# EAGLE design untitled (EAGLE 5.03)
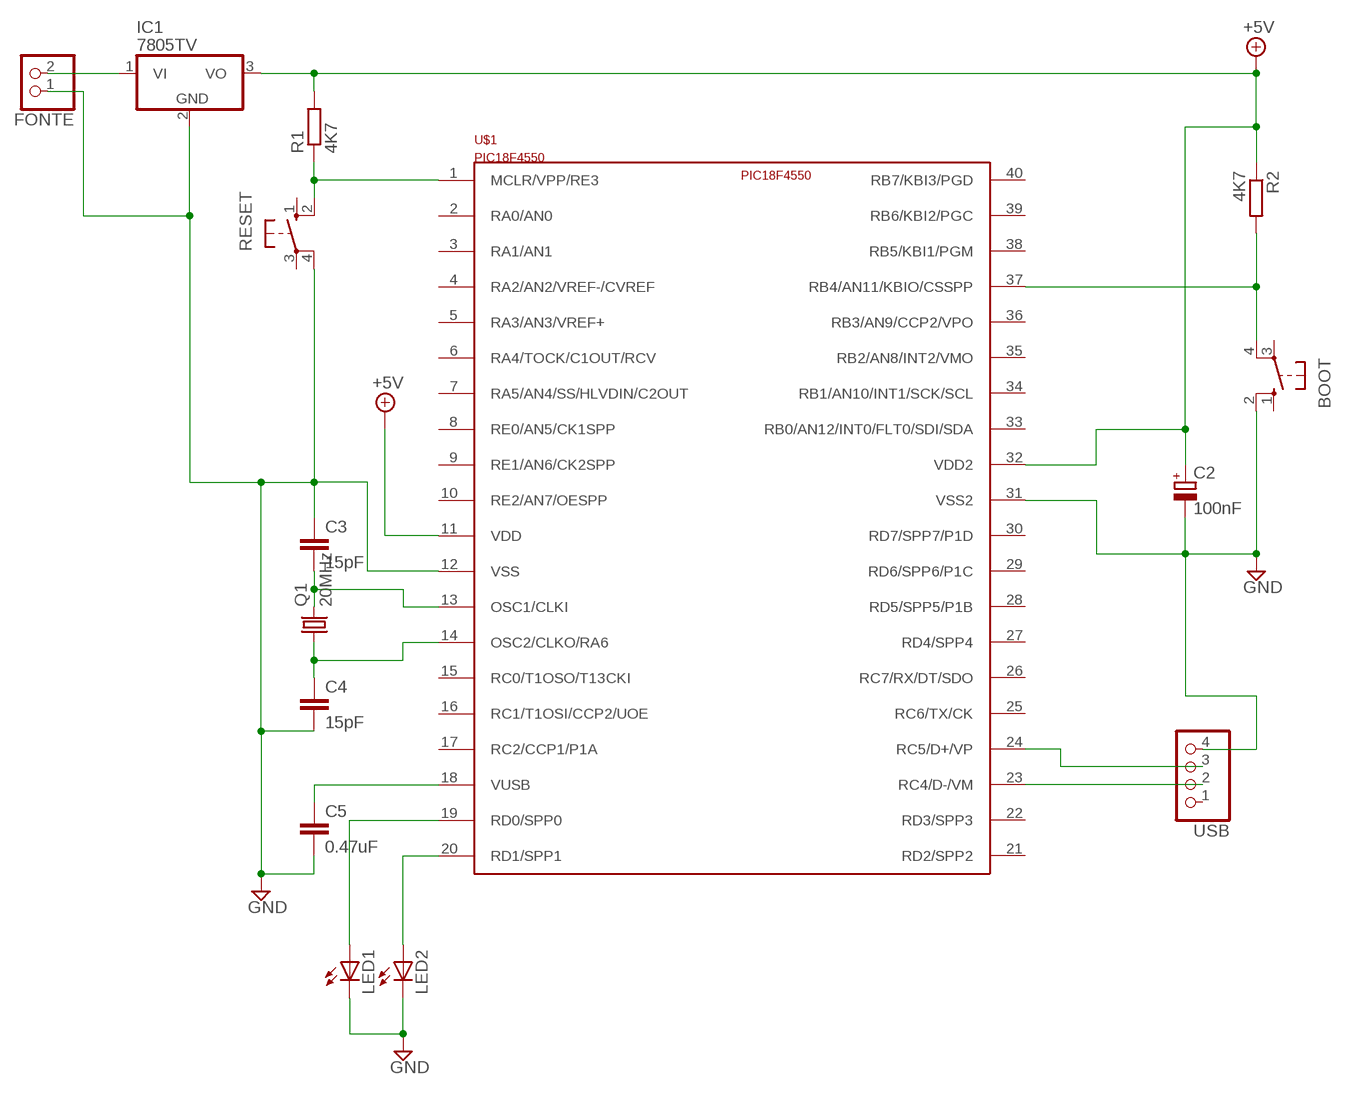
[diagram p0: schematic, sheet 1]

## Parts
BOOT  10-XX  [B3F-10XX]
C2  100nF  CPOL-EUE2,5-6E  [E2,5-6E]
C3  15pF  C-EU025-030X050  [C025-030X050]
C4  15pF  C-EU025-030X050  [C025-030X050]
C5  0.47uF  C-EU025-030X050  [C025-030X050]
FONTE  PINHD-1X2  [1X02]
IC1  7805TV  [TO220V]
LED1  LED5MM  [LED5MM]
LED2  LED5MM  [LED5MM]
Q1  20MHz  CRYSTALHC49S  [HC49/S]
R1  4K7  R-EU_0207/10  [0207/10]
R2  4K7  R-EU_0207/10  [0207/10]
RESET  10-XX  [B3F-10XX]
U$1  PIC18F4550  [PDIP-40]
USB  PINHD-1X4  [1X04]

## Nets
+5V: C2.+ IC1.3(VO) R1.2 R2.1 U$1.11(VDD) U$1.32(VDD2)
GND: BOOT.2(S1) C2.- C3.1 C4.2 C5.2 FONTE.1 IC1.2(GND) LED1.K(C) LED2.K(C) RESET.4(P1) U$1.12(VSS) U$1.31(VSS2) USB.4
N$1: C3.2 Q1.2 U$1.13(OSC1/CLKI)
N$2: C4.1 Q1.1 U$1.14(OSC2/CLKO/RA6)
N$3: R1.1 RESET.2(S1) U$1.1(MCLR/VPP/RE3)
N$4: FONTE.2 IC1.1(VI)
N$5: C5.1 U$1.18(VUSB)
N$8: U$1.23(RC4/D-/VM) USB.2
N$9: U$1.24(RC5/D+/VP) USB.3
N$10: LED1.A U$1.19(RD0/SPP0)
N$11: BOOT.4(P1) R2.2 U$1.37(RB4/AN11/KBIO/CSSPP)
N$12: LED2.A U$1.20(RD1/SPP1)
Unconnected: BOOT.1(S) BOOT.3(P) RESET.1(S) RESET.3(P) U$1.2(RA0/AN0) U$1.3(RA1/AN1) U$1.4(RA2/AN2/VREF-/CVREF) U$1.5(RA3/AN3/VREF+) U$1.6(RA4/TOCK/C1OUT/RCV) U$1.7(RA5/AN4/SS/HLVDIN/C2OUT) U$1.8(RE0/AN5/CK1SPP) U$1.9(RE1/AN6/CK2SPP) U$1.10(RE2/AN7/OESPP) U$1.15(RC0/T1OSO/T13CKI) U$1.16(RC1/T1OSI/CCP2/UOE) U$1.17(RC2/CCP1/P1A) U$1.21(RD2/SPP2) U$1.22(RD3/SPP3) U$1.25(RC6/TX/CK) U$1.26(RC7/RX/DT/SDO) U$1.27(RD4/SPP4) U$1.28(RD5/SPP5/P1B) U$1.29(RD6/SPP6/P1C) U$1.30(RD7/SPP7/P1D) U$1.33(RB0/AN12/INT0/FLT0/SDI/SDA) U$1.34(RB1/AN10/INT1/SCK/SCL) U$1.35(RB2/AN8/INT2/VMO) U$1.36(RB3/AN9/CCP2/VPO) U$1.38(RB5/KBI1/PGM) U$1.39(RB6/KBI2/PGC) U$1.40(RB7/KBI3/PGD) USB.1

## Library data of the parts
BOOT RESET = switch-omron:10-XX: OMRON SWITCH
C2 = resistor:CPOL-EU: POLARIZED CAPACITOR, European symbol
C3-C5 = resistor:C-EU: CAPACITOR, European symbol
FONTE = pinhead:PINHD-1X2: PIN HEADER
IC1 = linear:78*: Positive VOLTAGE REGULATOR Source: http://cache.national.com/ds/LM/LM78L05.pdf http://www.fairchildsemi.com/ds/LM/LM7805.pdf
LED1 LED2 = led:LED: LED
Q1 = crystal:CRYSTAL: CRYSTAL
R1 R2 = resistor:R-EU_: RESISTOR, European symbol
U$1 = pic18f4550:PIC18F4550
USB = pinhead:PINHD-1X4: PIN HEADER

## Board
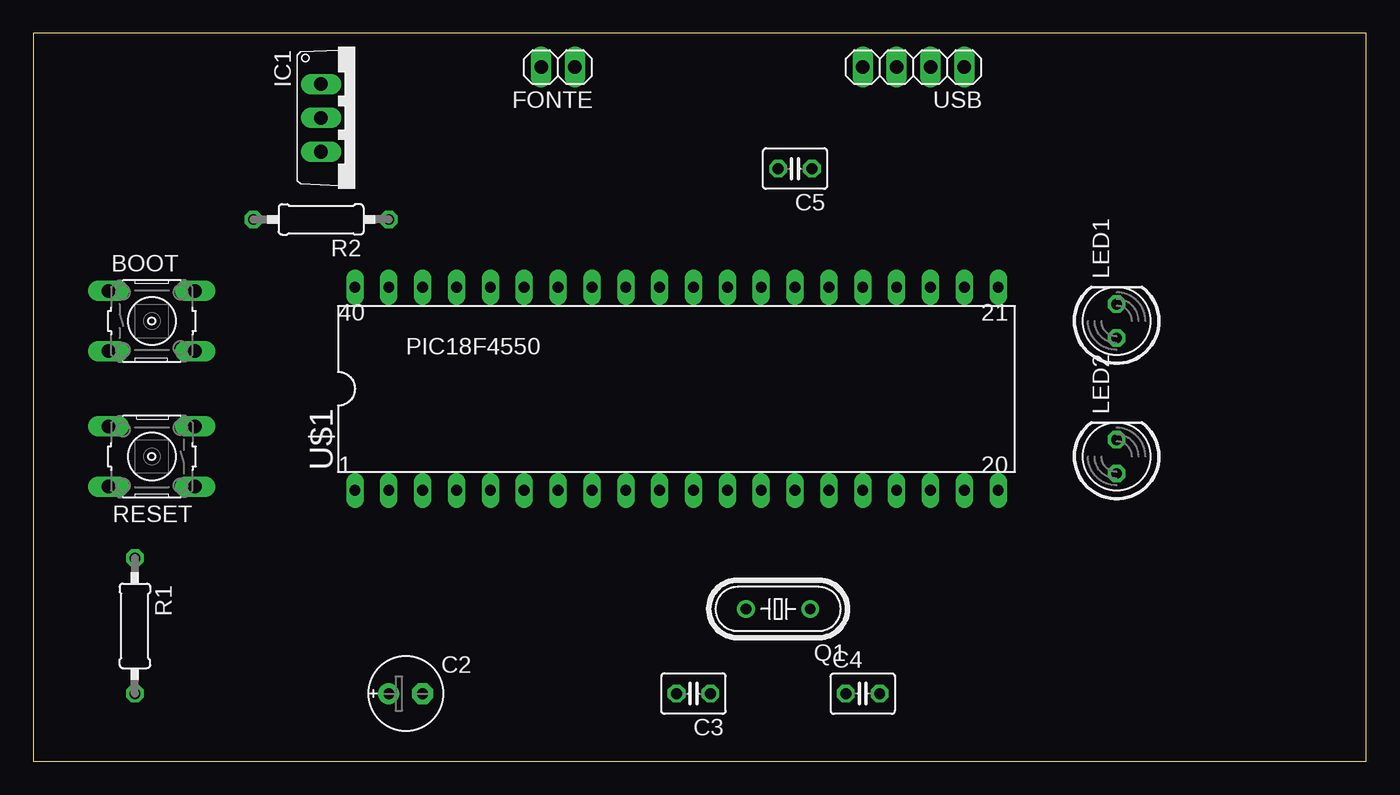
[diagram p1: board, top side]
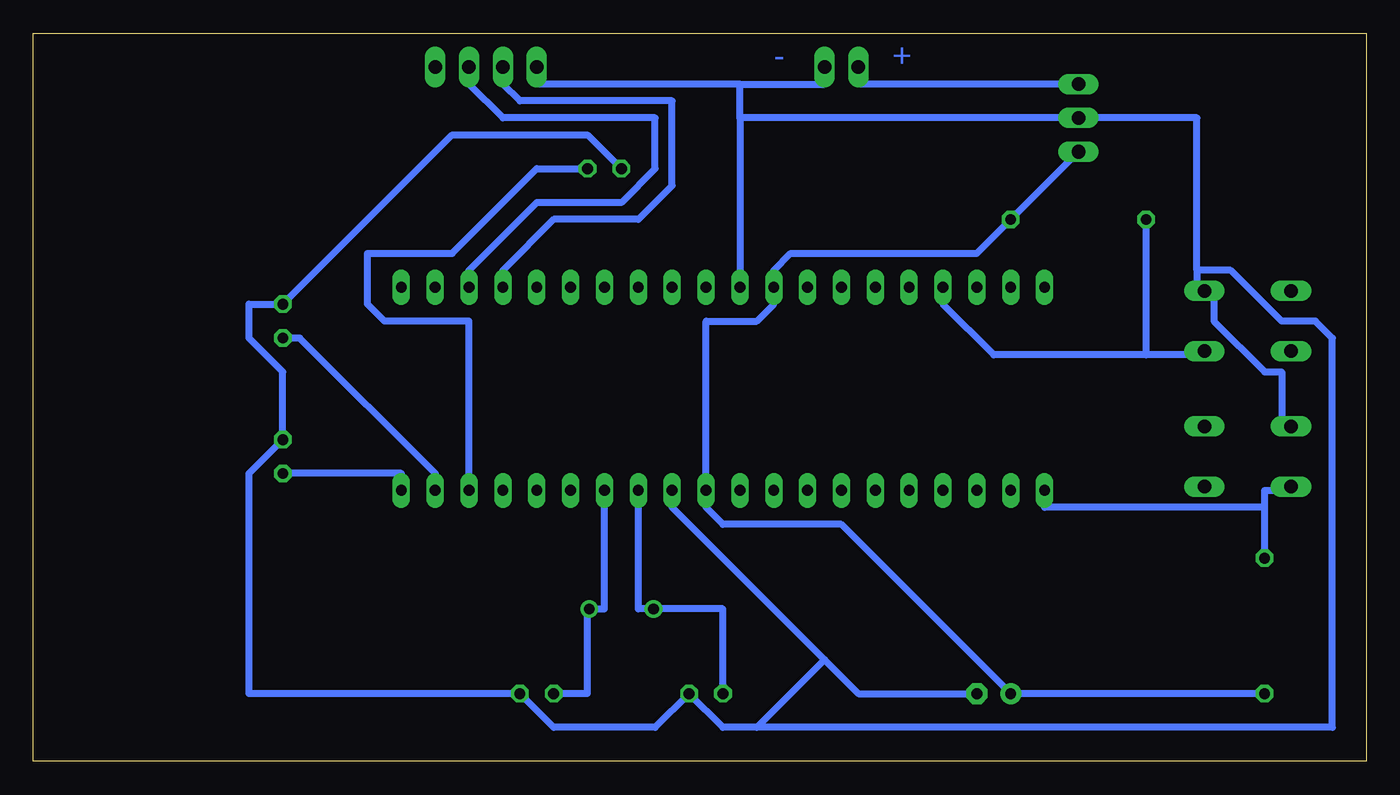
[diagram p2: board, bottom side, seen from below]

Size 100 x 54.6 mm. Coordinates in mm from the lower left corner, seen from the top.
Outline: 0,0 100,0 100,54.6 0,54.6 0,0
Copper layers (1*16): Top 0.035mm / dielectric 1.5mm / Bottom 0.035mm
Design rules "default *": minimum track width 20mil, minimum drill 24mil, track to track 20mil, track to pad 20mil, pad to pad 20mil, via to via 8mil, smd to smd 8mil, copper to edge 40mil, drill to drill 8mil, minimum pad ring 10mil, minimum via ring 8mil, stop-mask expansion 4mil, vias tented up to drill 0mil, thermal gap 10mil

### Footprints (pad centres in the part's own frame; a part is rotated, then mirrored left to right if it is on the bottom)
B3F-10XX = drill 1.016 long: 1 -3.251,2.261; 2 3.251,2.261; 3 -3.251,-2.261; 4 3.251,-2.261
E2,5-6E = drill 0.813 pad 1.575 round: + -1.27,0 | drill 0.813 pad 1.575 octagon: - 1.27,0
C025-030X050 = drill 0.813 octagon: 1 -1.27,0; 2 1.27,0
1X02 = drill 1.016 long: 1 -1.27,0; 2 1.27,0
TO220V = drill 1.016 long: 1 -2.54,-2.54; 2 0,-2.54; 3 2.54,-2.54
LED5MM = drill 0.813 octagon: A -1.27,0; K 1.27,0
HC49/S = drill 0.813 round: 1 -2.413,0; 2 2.413,0
0207/10 = drill 0.813 octagon: 1 -5.08,0; 2 5.08,0
PDIP-40 = drill 0.813 long: 1 -19.05,-8.89; 2 -16.51,-8.89; 3 -13.97,-8.89; 4 -11.43,-8.89; 5 -8.89,-8.89; 6 -6.35,-8.89; 7 -3.81,-8.89; 8 -1.27,-8.89; 9 1.27,-8.89; 10 3.81,-8.89; 11 6.35,-8.89; 12 8.89,-8.89; 13 11.43,-8.89; 14 13.97,-8.89; 15 16.51,-8.89; 16 19.05,-8.89; 17 21.59,-8.89; 18 24.13,-8.89; 19 26.67,-8.89; 20 29.21,-8.89; 21 29.21,6.35; 22 26.67,6.35; 23 24.13,6.35; 24 21.59,6.35; 25 19.05,6.35; 26 16.51,6.35; 27 13.97,6.35; 28 11.43,6.35; 29 8.89,6.35; 30 6.35,6.35; 31 3.81,6.35; 32 1.27,6.35; 33 -1.27,6.35; 34 -3.81,6.35; 35 -6.35,6.35; 36 -8.89,6.35; 37 -11.43,6.35; 38 -13.97,6.35; 39 -16.51,6.35; 40 -19.05,6.35
1X04 = drill 1.016 long: 1 -3.81,0; 2 -1.27,0; 3 1.27,0; 4 3.81,0

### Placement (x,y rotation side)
BOOT  8.89,33.02 0 top
C2  27.94,5.08 0 top
C3  49.53,5.08 180 top
C4  62.23,5.08 0 top
C5  57.15,44.45 180 top
FONTE  39.37,52.07 180 top
IC1  24.13,48.26 270 top
LED1  81.28,33.02 90 top
LED2  81.28,22.86 90 top
Q1  55.88,11.43 180 top
R1  7.62,10.16 270 top
R2  21.59,40.64 180 top
RESET  8.89,22.86 180 top
U$1  43.18,29.21 0 top
USB  66.04,52.07 180 top

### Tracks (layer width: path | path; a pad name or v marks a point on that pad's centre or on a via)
+5V
  Bottom 0.508: R1.2 C2.+ 39.37,17.78 48.26,17.78 49.53,19.05 U$1.11 49.53,33.02 45.72,33.02 44.45,34.29 U$1.32 44.45,36.83 43.18,38.1 29.21,38.1 R2.1 IC1.3
GND
  Bottom 0.508: RESET.4 6.35,25.4 6.35,29.21 7.62,29.21 11.43,33.02 11.43,35.56 BOOT.2 12.7,35.56 12.7,36.83 | 46.99,48.26 46.99,50.8 | 46.99,50.8 40.64,50.8 FONTE.1 | 46.99,48.26 U$1.31 | 46.99,48.26 IC1.2 12.7,48.26 12.7,36.83 | 46.99,50.8 62.23,50.8 USB.4 | C5.2 58.42,46.99 68.58,46.99 LED1.K 83.82,34.29 83.82,31.75 81.28,29.21 LED2.K 83.82,21.59 83.82,5.08 C4.2 60.96,2.54 53.34,2.54 C3.1 48.26,2.54 45.72,2.54 | 40.64,7.62 38.1,5.08 C2.- | 40.64,7.62 52.07,19.05 U$1.12 | 45.72,2.54 40.64,7.62 | 12.7,36.83 10.16,36.83 6.35,33.02 3.81,33.02 2.54,31.75 2.54,2.54 45.72,2.54
N$1
  Bottom 0.508: C3.2 48.26,11.43 53.34,11.43 Q1.2 54.61,11.43 U$1.13
N$2
  Bottom 0.508: C4.1 58.42,5.08 58.42,11.43 Q1.1 57.15,11.43 U$1.14
N$3
  Bottom 0.508: 7.62,19.05 7.62,20.32 6.35,20.32 RESET.2 | R1.1 7.62,19.05 | 7.62,19.05 24.13,19.05 U$1.1
N$4
  Bottom 0.508: IC1.1 38.1,50.8 FONTE.2
N$5
  Bottom 0.508: C5.1 62.23,44.45 68.58,38.1 74.93,38.1 74.93,34.29 73.66,33.02 67.31,33.02 U$1.18
N$8
  Bottom 0.508: U$1.23 67.31,36.83 62.23,41.91 55.88,41.91 53.34,44.45 53.34,48.26 64.77,48.26 67.31,50.8 USB.2
N$9
  Bottom 0.508: U$1.24 64.77,36.83 60.96,40.64 54.61,40.64 52.07,43.18 52.07,49.53 63.5,49.53 64.77,50.8 USB.3
N$10
  Bottom 0.508: LED1.A 80.01,31.75 69.85,21.59 U$1.19
N$11
  Bottom 0.508: 16.51,30.48 12.7,30.48 BOOT.4 | 16.51,30.48 27.94,30.48 31.75,34.29 U$1.37 | 16.51,30.48 R2.2
N$12
  Bottom 0.508: LED2.A 72.39,21.59 U$1.20

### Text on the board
Bottom: + | -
